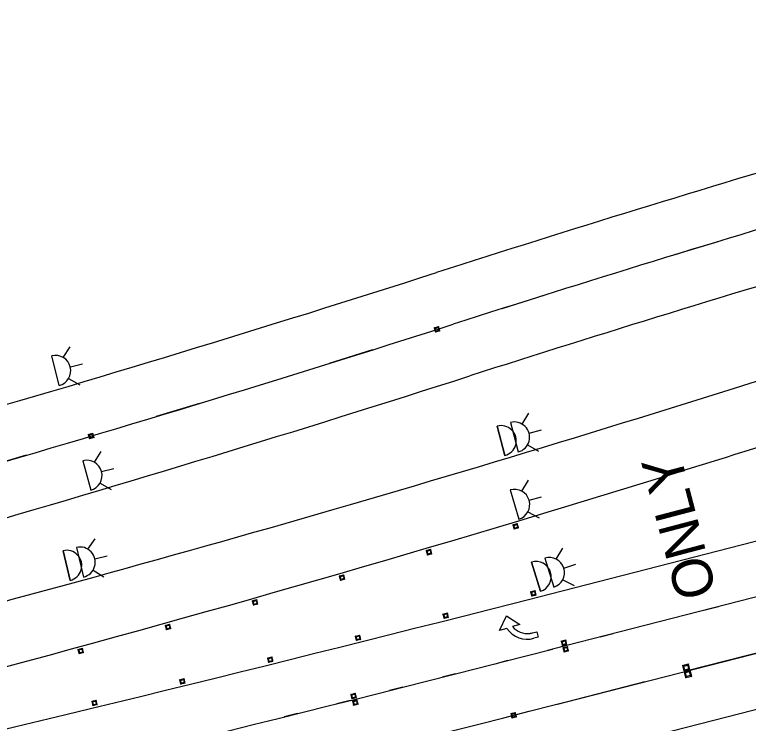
# Model space of a CAD drawing. Extents: x 2471014 to 2497726, y 6959577 to 6980268.
# Drawn here: x 2486454.1 to 2486616.2, y 6968531.5 to 6968688.1 of the extents above; entities that cross this region are included whole.
import ezdxf

# ---------------------------------------------------------------- set-up
doc = ezdxf.new("R2010")
doc.units = 0
for name, color, linetype in [('1', 7, 'Continuous'), ('13', 7, 'Continuous'), ('18', 7, 'Continuous'), ('23', 7, 'Continuous'), ('25', 7, 'Continuous'), ('5', 7, 'Continuous'), ('59', 7, 'Continuous'), ('C-ANNO-NOTE', 7, 'Continuous'), ('C-COMM-IDEN', 7, 'Continuous'), ('Level 30', 7, 'Continuous'), ('Level 40', 7, 'Continuous'), ('p_structure fence', 7, 'Continuous'), ('p_structure wall', 7, 'Continuous'), ('PMK_Del_D-SY_SZ_TYC_CTB', 7, 'Continuous'), ('RDWY_PAVE_XSTREET_FOC', 7, 'Continuous'), ('V7_25', 7, 'Continuous')]:
    doc.layers.add(name, color=color, linetype=linetype)

msp = doc.modelspace()

# ---------------------------------------------------------------- linework, layer by layer
at = {"layer": '1'}
for p, q in [((2486609.48, 6968637.96), (2486599.91, 6968635.05)), ((2486571.26, 6968626.15), (2486561.73, 6968623.14)), ((2486533.14, 6968614.04), (2486523.6, 6968611.05)), ((2486494.93, 6968602.21), (2486485.36, 6968599.31)), ((2486456.61, 6968590.75), (2486447.01, 6968587.94))]:
    msp.add_line(p, q, dxfattribs=at)
at = {"layer": '13'}
for centre, radius, start, end in [((2487770.88, 6964812.37), 3986, 105.11172, 107.76526), ((2485323.83, 6972449.93), 4034, 284.37494, 287.76526), ((2485407.99, 6972430.21), 4024, 286.71744, 287.75395)]:
    msp.add_arc(centre, radius, start, end, dxfattribs=at)
at = {"layer": '18'}
msp.add_line((2486569.97, 6968559.51), (2486887.36, 6968640.85), dxfattribs=at)
for centre, start, end in [((2487770.88, 6964812.37), 105.11172, 107.76526), ((2485323.83, 6972449.93), 284.37494, 287.76526), ((2485407.99, 6972430.21), 284.37494, 287.75395)]:
    msp.add_arc(centre, 4010, start, end, dxfattribs=at)
at = {"layer": '23'}
for p, q in [((2486546.8, 6968618.92), (2486547.76, 6968619.23)), ((2486547.01, 6968618.8), (2486546.8, 6968618.92)), ((2486546.8, 6968618.92), (2486547.1, 6968617.95)), ((2486547.76, 6968619.23), (2486547.66, 6968619.01)), ((2486547.66, 6968619.01), (2486547.86, 6968618.36)), ((2486547.99, 6968618.52), (2486547.76, 6968619.23)), ((2486547.18, 6968618.29), (2486547.01, 6968618.8)), ((2486548.07, 6968618.26), (2486547.1, 6968617.95)), ((2486547.1, 6968617.95), (2486547.22, 6968618.15)), ((2486547.22, 6968618.15), (2486547.18, 6968618.29)), ((2486547.86, 6968618.36), (2486548.07, 6968618.26)), ((2486548.07, 6968618.26), (2486547.99, 6968618.52)), ((2486470.36, 6968595.35), (2486471.33, 6968595.64)), ((2486470.57, 6968595.23), (2486470.36, 6968595.35)), ((2486470.36, 6968595.35), (2486470.65, 6968594.38)), ((2486470.72, 6968594.72), (2486470.57, 6968595.23)), ((2486471.62, 6968594.67), (2486470.65, 6968594.38)), ((2486470.65, 6968594.38), (2486470.77, 6968594.58)), ((2486470.77, 6968594.58), (2486470.72, 6968594.72)), ((2486471.33, 6968595.64), (2486471.22, 6968595.42)), ((2486471.22, 6968595.42), (2486471.41, 6968594.77)), ((2486471.54, 6968594.93), (2486471.33, 6968595.64)), ((2486471.41, 6968594.77), (2486471.62, 6968594.67)), ((2486471.62, 6968594.67), (2486471.54, 6968594.93)), ((2486564.2, 6968575.39), (2486565.17, 6968575.68)), ((2486564.41, 6968575.27), (2486564.2, 6968575.39)), ((2486564.2, 6968575.39), (2486564.49, 6968574.42)), ((2486564.57, 6968574.75), (2486564.41, 6968575.27)), ((2486565.17, 6968575.68), (2486565.06, 6968575.46)), ((2486565.06, 6968575.46), (2486565.25, 6968574.81)), ((2486565.38, 6968574.97), (2486565.17, 6968575.68)), ((2486565.46, 6968574.71), (2486564.49, 6968574.42)), ((2486564.49, 6968574.42), (2486564.61, 6968574.62)), ((2486564.61, 6968574.62), (2486564.57, 6968574.75)), ((2486565.25, 6968574.81), (2486565.46, 6968574.71)), ((2486565.46, 6968574.71), (2486565.38, 6968574.97)), ((2486545.03, 6968569.69), (2486546, 6968569.98)), ((2486545.24, 6968569.57), (2486545.03, 6968569.69)), ((2486545.03, 6968569.69), (2486545.32, 6968568.72)), ((2486545.39, 6968569.05), (2486545.24, 6968569.57)), ((2486546.29, 6968569), (2486545.32, 6968568.72)), ((2486545.32, 6968568.72), (2486545.43, 6968568.92)), ((2486545.43, 6968568.92), (2486545.39, 6968569.05)), ((2486546, 6968569.98), (2486545.89, 6968569.76)), ((2486545.89, 6968569.76), (2486546.08, 6968569.11)), ((2486546.21, 6968569.26), (2486546, 6968569.98)), ((2486546.08, 6968569.11), (2486546.29, 6968569)), ((2486546.29, 6968569), (2486546.21, 6968569.26)), ((2486525.83, 6968564.09), (2486526.81, 6968564.37)), ((2486526.04, 6968563.97), (2486525.83, 6968564.09)), ((2486525.83, 6968564.09), (2486526.11, 6968563.11)), ((2486526.19, 6968563.45), (2486526.04, 6968563.97)), ((2486526.81, 6968564.37), (2486526.7, 6968564.15)), ((2486526.7, 6968564.15), (2486526.88, 6968563.5)), ((2486527.01, 6968563.65), (2486526.81, 6968564.37)), ((2486527.09, 6968563.4), (2486526.11, 6968563.11)), ((2486526.11, 6968563.11), (2486526.23, 6968563.31)), ((2486526.23, 6968563.31), (2486526.19, 6968563.45)), ((2486526.88, 6968563.5), (2486527.09, 6968563.4)), ((2486527.09, 6968563.4), (2486527.01, 6968563.65)), ((2486568.13, 6968560.6), (2486569.12, 6968560.85)), ((2486568.34, 6968560.47), (2486568.13, 6968560.6)), ((2486568.13, 6968560.6), (2486568.38, 6968559.62)), ((2486569.12, 6968560.85), (2486569, 6968560.64)), ((2486569, 6968560.64), (2486569.16, 6968559.98)), ((2486569.3, 6968560.13), (2486569.12, 6968560.85)), ((2486568.47, 6968559.95), (2486568.34, 6968560.47)), ((2486569.37, 6968559.87), (2486568.38, 6968559.62)), ((2486568.38, 6968559.62), (2486568.51, 6968559.82)), ((2486568.51, 6968559.82), (2486568.47, 6968559.95)), ((2486569.16, 6968559.98), (2486569.37, 6968559.87)), ((2486569.37, 6968559.87), (2486569.3, 6968560.13)), ((2486506.61, 6968558.58), (2486507.58, 6968558.86)), ((2486506.82, 6968558.46), (2486506.61, 6968558.58)), ((2486506.61, 6968558.58), (2486506.88, 6968557.61)), ((2486506.97, 6968557.94), (2486506.82, 6968558.46)), ((2486507.86, 6968557.88), (2486506.88, 6968557.61)), ((2486506.88, 6968557.61), (2486507.01, 6968557.81)), ((2486507.01, 6968557.81), (2486506.97, 6968557.94)), ((2486507.58, 6968558.86), (2486507.47, 6968558.64)), ((2486507.47, 6968558.64), (2486507.66, 6968557.99)), ((2486507.79, 6968558.14), (2486507.58, 6968558.86)), ((2486507.66, 6968557.99), (2486507.86, 6968557.88)), ((2486507.86, 6968557.88), (2486507.79, 6968558.14)), ((2486548.75, 6968555.67), (2486549.73, 6968555.92)), ((2486548.96, 6968555.54), (2486548.75, 6968555.67)), ((2486548.75, 6968555.67), (2486549, 6968554.69)), ((2486549.73, 6968555.92), (2486549.62, 6968555.71)), ((2486549.62, 6968555.71), (2486549.78, 6968555.05)), ((2486549.92, 6968555.2), (2486549.73, 6968555.92)), ((2486549.09, 6968555.02), (2486548.96, 6968555.54)), ((2486549.98, 6968554.94), (2486549, 6968554.69)), ((2486549, 6968554.69), (2486549.13, 6968554.88)), ((2486549.13, 6968554.88), (2486549.09, 6968555.02)), ((2486549.78, 6968555.05), (2486549.98, 6968554.94)), ((2486549.98, 6968554.94), (2486549.92, 6968555.2)), ((2486487.36, 6968553.17), (2486488.33, 6968553.44)), ((2486487.57, 6968553.05), (2486487.36, 6968553.17)), ((2486487.36, 6968553.17), (2486487.63, 6968552.19)), ((2486487.71, 6968552.53), (2486487.57, 6968553.05)), ((2486488.61, 6968552.47), (2486487.63, 6968552.19)), ((2486487.75, 6968552.39), (2486487.71, 6968552.53)), ((2486488.33, 6968553.44), (2486488.22, 6968553.23)), ((2486488.22, 6968553.23), (2486488.4, 6968552.57)), ((2486488.53, 6968552.73), (2486488.33, 6968553.44)), ((2486488.4, 6968552.57), (2486488.61, 6968552.47)), ((2486488.61, 6968552.47), (2486488.53, 6968552.73)), ((2486487.63, 6968552.19), (2486487.75, 6968552.39)), ((2486529.36, 6968550.78), (2486530.34, 6968551.03)), ((2486529.57, 6968550.65), (2486529.36, 6968550.78)), ((2486529.36, 6968550.78), (2486529.6, 6968549.8)), ((2486530.34, 6968551.03), (2486530.22, 6968550.82)), ((2486530.22, 6968550.82), (2486530.39, 6968550.16)), ((2486530.52, 6968550.31), (2486530.34, 6968551.03)), ((2486529.7, 6968550.13), (2486529.57, 6968550.65)), ((2486530.59, 6968550.05), (2486529.6, 6968549.8)), ((2486529.6, 6968549.8), (2486529.73, 6968550)), ((2486529.73, 6968550), (2486529.7, 6968550.13)), ((2486530.39, 6968550.16), (2486530.59, 6968550.05)), ((2486530.59, 6968550.05), (2486530.52, 6968550.31)), ((2486574.9, 6968549.69), (2486575.89, 6968549.94)), ((2486575.11, 6968549.56), (2486574.9, 6968549.69)), ((2486574.9, 6968549.69), (2486575.16, 6968548.71)), ((2486575.25, 6968549.04), (2486575.11, 6968549.56)), ((2486575.89, 6968549.94), (2486575.77, 6968549.73)), ((2486575.77, 6968549.73), (2486575.94, 6968549.07)), ((2486576.07, 6968549.22), (2486575.89, 6968549.94)), ((2486576.14, 6968548.96), (2486576.07, 6968549.22)), ((2486468.08, 6968547.86), (2486469.06, 6968548.12)), ((2486468.29, 6968547.73), (2486468.08, 6968547.86)), ((2486468.08, 6968547.86), (2486468.35, 6968546.88)), ((2486468.43, 6968547.21), (2486468.29, 6968547.73)), ((2486469.06, 6968548.12), (2486468.94, 6968547.91)), ((2486468.94, 6968547.91), (2486469.12, 6968547.25)), ((2486469.25, 6968547.4), (2486469.06, 6968548.12)), ((2486576.14, 6968548.96), (2486575.16, 6968548.71)), ((2486575.16, 6968548.71), (2486575.28, 6968548.9)), ((2486575.28, 6968548.9), (2486575.25, 6968549.04)), ((2486575.28, 6968548.24), (2486576.26, 6968548.49)), ((2486575.48, 6968548.11), (2486575.28, 6968548.24)), ((2486575.28, 6968548.24), (2486575.53, 6968547.25)), ((2486575.62, 6968547.59), (2486575.48, 6968548.11)), ((2486575.65, 6968547.45), (2486575.62, 6968547.59)), ((2486575.94, 6968549.07), (2486576.14, 6968548.96)), ((2486576.26, 6968548.49), (2486576.14, 6968548.28)), ((2486576.14, 6968548.28), (2486576.31, 6968547.62)), ((2486576.44, 6968547.77), (2486576.26, 6968548.49)), ((2486576.31, 6968547.62), (2486576.51, 6968547.51)), ((2486576.51, 6968547.51), (2486576.44, 6968547.77)), ((2486469.33, 6968547.14), (2486468.35, 6968546.88)), ((2486468.35, 6968546.88), (2486468.47, 6968547.08)), ((2486468.47, 6968547.08), (2486468.43, 6968547.21)), ((2486469.12, 6968547.25), (2486469.33, 6968547.14)), ((2486469.33, 6968547.14), (2486469.25, 6968547.4)), ((2486509.95, 6968545.94), (2486510.94, 6968546.19)), ((2486510.16, 6968545.81), (2486509.95, 6968545.94)), ((2486509.95, 6968545.94), (2486510.2, 6968544.96)), ((2486510.94, 6968546.19), (2486510.82, 6968545.98)), ((2486510.82, 6968545.98), (2486510.98, 6968545.32)), ((2486511.12, 6968545.47), (2486510.94, 6968546.19)), ((2486576.51, 6968547.51), (2486575.53, 6968547.25)), ((2486575.53, 6968547.25), (2486575.65, 6968547.45)), ((2486510.29, 6968545.29), (2486510.16, 6968545.81)), ((2486511.18, 6968545.21), (2486510.2, 6968544.96)), ((2486510.2, 6968544.96), (2486510.32, 6968545.16)), ((2486510.32, 6968545.16), (2486510.29, 6968545.29)), ((2486510.98, 6968545.32), (2486511.18, 6968545.21)), ((2486511.18, 6968545.21), (2486511.12, 6968545.47)), ((2486601.71, 6968544.33), (2486603.02, 6968544.66)), ((2486601.98, 6968544.18), (2486601.71, 6968544.33)), ((2486601.71, 6968544.33), (2486601.8, 6968543.98)), ((2486603.02, 6968544.66), (2486602.85, 6968544.4)), ((2486602.85, 6968544.4), (2486602.9, 6968544.22)), ((2486603.35, 6968543.35), (2486603.02, 6968544.66)), ((2486601.8, 6968543.98), (2486602.04, 6968543.02)), ((2486602.2, 6968543.3), (2486601.98, 6968544.18)), ((2486603.35, 6968543.35), (2486602.04, 6968543.02)), ((2486602.04, 6968543.02), (2486602.2, 6968543.3)), ((2486602.08, 6968542.87), (2486603.39, 6968543.21)), ((2486602.35, 6968542.72), (2486602.08, 6968542.87)), ((2486602.08, 6968542.87), (2486602.17, 6968542.53)), ((2486602.57, 6968541.85), (2486602.35, 6968542.72)), ((2486602.9, 6968544.22), (2486603.08, 6968543.53)), ((2486603.08, 6968543.53), (2486603.35, 6968543.35)), ((2486603.39, 6968543.21), (2486603.22, 6968542.95)), ((2486603.22, 6968542.95), (2486603.27, 6968542.76)), ((2486603.27, 6968542.76), (2486603.45, 6968542.07)), ((2486603.73, 6968541.9), (2486603.39, 6968543.21)), ((2486490.54, 6968541.15), (2486491.52, 6968541.39)), ((2486490.75, 6968541.02), (2486490.54, 6968541.15)), ((2486490.54, 6968541.15), (2486490.78, 6968540.17)), ((2486491.52, 6968541.39), (2486491.4, 6968541.18)), ((2486491.4, 6968541.18), (2486491.56, 6968540.52)), ((2486491.7, 6968540.67), (2486491.52, 6968541.39)), ((2486602.17, 6968542.53), (2486602.42, 6968541.56)), ((2486603.73, 6968541.9), (2486602.42, 6968541.56)), ((2486602.42, 6968541.56), (2486602.57, 6968541.85)), ((2486603.45, 6968542.07), (2486603.73, 6968541.9)), ((2486490.87, 6968540.5), (2486490.75, 6968541.02)), ((2486491.77, 6968540.41), (2486490.78, 6968540.17)), ((2486490.78, 6968540.17), (2486490.91, 6968540.36)), ((2486490.91, 6968540.36), (2486490.87, 6968540.5)), ((2486491.56, 6968540.52), (2486491.77, 6968540.41)), ((2486491.77, 6968540.41), (2486491.7, 6968540.67)), ((2486528.38, 6968537.91), (2486529.36, 6968538.16)), ((2486528.58, 6968537.78), (2486528.38, 6968537.91)), ((2486528.38, 6968537.91), (2486528.62, 6968536.93)), ((2486529.36, 6968538.16), (2486529.24, 6968537.94)), ((2486529.24, 6968537.94), (2486529.4, 6968537.29)), ((2486529.54, 6968537.43), (2486529.36, 6968538.16)), ((2486471.11, 6968536.4), (2486472.1, 6968536.64)), ((2486471.32, 6968536.27), (2486471.11, 6968536.4)), ((2486471.11, 6968536.4), (2486471.35, 6968535.42)), ((2486471.44, 6968535.75), (2486471.32, 6968536.27)), ((2486472.1, 6968536.64), (2486471.98, 6968536.43)), ((2486471.98, 6968536.43), (2486472.14, 6968535.77)), ((2486472.27, 6968535.92), (2486472.1, 6968536.64)), ((2486528.71, 6968537.26), (2486528.58, 6968537.78)), ((2486529.61, 6968537.17), (2486528.62, 6968536.93)), ((2486528.62, 6968536.93), (2486528.75, 6968537.12)), ((2486528.75, 6968537.12), (2486528.71, 6968537.26)), ((2486528.75, 6968536.46), (2486529.73, 6968536.7)), ((2486528.96, 6968536.33), (2486528.75, 6968536.46)), ((2486528.75, 6968536.46), (2486528.99, 6968535.47)), ((2486529.09, 6968535.81), (2486528.96, 6968536.33)), ((2486529.4, 6968537.29), (2486529.61, 6968537.17)), ((2486529.61, 6968537.17), (2486529.54, 6968537.43)), ((2486529.73, 6968536.7), (2486529.61, 6968536.49)), ((2486529.61, 6968536.49), (2486529.78, 6968535.83)), ((2486529.91, 6968535.98), (2486529.73, 6968536.7)), ((2486472.34, 6968535.66), (2486471.35, 6968535.42)), ((2486471.35, 6968535.42), (2486471.48, 6968535.61)), ((2486471.48, 6968535.61), (2486471.44, 6968535.75)), ((2486472.14, 6968535.77), (2486472.34, 6968535.66)), ((2486472.34, 6968535.66), (2486472.27, 6968535.92)), ((2486529.98, 6968535.72), (2486528.99, 6968535.47)), ((2486528.99, 6968535.47), (2486529.12, 6968535.67)), ((2486529.12, 6968535.67), (2486529.09, 6968535.81)), ((2486529.78, 6968535.83), (2486529.98, 6968535.72)), ((2486529.98, 6968535.72), (2486529.91, 6968535.98)), ((2486563.73, 6968533.66), (2486564.72, 6968533.91)), ((2486563.94, 6968533.55), (2486563.73, 6968533.66)), ((2486563.73, 6968533.66), (2486563.8, 6968533.4)), ((2486563.8, 6968533.4), (2486563.98, 6968532.68)), ((2486564.1, 6968532.89), (2486563.94, 6968533.55)), ((2486564.72, 6968533.91), (2486564.59, 6968533.71)), ((2486564.59, 6968533.71), (2486564.63, 6968533.58)), ((2486564.63, 6968533.58), (2486564.76, 6968533.06)), ((2486564.97, 6968532.93), (2486564.72, 6968533.91)), ((2486564.76, 6968533.06), (2486564.97, 6968532.93)), ((2486564.97, 6968532.93), (2486563.98, 6968532.68)), ((2486563.98, 6968532.68), (2486564.1, 6968532.89))]:
    msp.add_line(p, q, dxfattribs=at)
for points in [[(2486547.86, 6968618.36), (2486547.22, 6968618.15), (2486547.01, 6968618.8), (2486547.66, 6968619.01)], [(2486471.41, 6968594.77), (2486470.77, 6968594.58), (2486470.57, 6968595.23), (2486471.22, 6968595.42)], [(2486565.25, 6968574.81), (2486564.61, 6968574.62), (2486564.41, 6968575.27), (2486565.06, 6968575.46)], [(2486546.08, 6968569.11), (2486545.43, 6968568.92), (2486545.24, 6968569.57), (2486545.89, 6968569.76)], [(2486526.88, 6968563.5), (2486526.23, 6968563.31), (2486526.04, 6968563.97), (2486526.7, 6968564.15)], [(2486569.16, 6968559.98), (2486568.51, 6968559.82), (2486568.34, 6968560.47), (2486569, 6968560.64)], [(2486507.66, 6968557.99), (2486507.01, 6968557.81), (2486506.82, 6968558.46), (2486507.47, 6968558.64)], [(2486549.78, 6968555.05), (2486549.13, 6968554.88), (2486548.96, 6968555.54), (2486549.62, 6968555.71)], [(2486488.4, 6968552.57), (2486487.75, 6968552.39), (2486487.57, 6968553.05), (2486488.22, 6968553.23)], [(2486530.39, 6968550.16), (2486529.73, 6968550), (2486529.57, 6968550.65), (2486530.22, 6968550.82)], [(2486575.94, 6968549.07), (2486575.28, 6968548.9), (2486575.11, 6968549.56), (2486575.77, 6968549.73)], [(2486469.12, 6968547.25), (2486468.47, 6968547.08), (2486468.29, 6968547.73), (2486468.94, 6968547.91)], [(2486576.31, 6968547.62), (2486575.65, 6968547.45), (2486575.48, 6968548.11), (2486576.14, 6968548.28)], [(2486510.98, 6968545.32), (2486510.32, 6968545.16), (2486510.16, 6968545.81), (2486510.82, 6968545.98)], [(2486601.98, 6968544.18), (2486602.85, 6968544.4), (2486603.08, 6968543.53), (2486602.2, 6968543.3)], [(2486602.35, 6968542.72), (2486603.22, 6968542.95), (2486603.45, 6968542.07), (2486602.57, 6968541.85)], [(2486491.56, 6968540.52), (2486490.91, 6968540.36), (2486490.75, 6968541.02), (2486491.4, 6968541.18)], [(2486529.4, 6968537.29), (2486528.75, 6968537.12), (2486528.58, 6968537.78), (2486529.24, 6968537.94)], [(2486472.14, 6968535.77), (2486471.48, 6968535.61), (2486471.32, 6968536.27), (2486471.98, 6968536.43)], [(2486529.78, 6968535.83), (2486529.12, 6968535.67), (2486528.96, 6968536.33), (2486529.61, 6968536.49)], [(2486563.94, 6968533.55), (2486564.59, 6968533.71), (2486564.76, 6968533.06), (2486564.1, 6968532.89)]]:
    msp.add_lwpolyline(points, close=True, dxfattribs=at)
at = {"layer": '25'}
for centre, radius, start, end in [((2485407.99, 6972430.21), 4024, 284.37494, 286.71744), ((2484477.59, 6976736.03), 8440, 281.888901, 284.354026)]:
    msp.add_arc(centre, radius, start, end, dxfattribs=at)
at = {"layer": '5'}
msp.add_line((2486893.32, 6968617.6), (2486602.71, 6968543.12), dxfattribs=at)
msp.add_arc((2479474.04, 6969335.88), 8460, 6.37617, 6.37617, dxfattribs=at)
at = {"layer": '59'}
msp.add_line((2486622.21, 6968560.51), (2486572.95, 6968547.88), dxfattribs=at)
msp.add_arc((2484477.59, 6976736.03), 8452, 281.888901, 284.354075, dxfattribs=at)
at = {"layer": 'C-ANNO-NOTE'}
for centre, radius, start, end in [((2487770.88, 6964812.37), 3998, 105.11172, 107.76526), ((2485323.83, 6972449.93), 4022, 284.37494, 287.76526)]:
    msp.add_arc(centre, radius, start, end, dxfattribs=at)
at = {"layer": 'C-COMM-IDEN'}
for p, q in [((2486566.22, 6968597.67), (2486567.72, 6968600.05)), ((2486563.66, 6968598.01), (2486565.4, 6968591.49)), ((2486562.45, 6968590.7), (2486560.7, 6968597.22)), ((2486560.7, 6968597.22), (2486562.45, 6968590.7)), ((2486567.79, 6968595.62), (2486570.51, 6968596.35)), ((2486567.45, 6968593.06), (2486569.9, 6968591.69)), ((2486470.29, 6968569.98), (2486471.85, 6968572.32)), ((2486467.74, 6968570.39), (2486469.32, 6968563.82)), ((2486573.8, 6968567.81), (2486575.21, 6968570.25)), ((2486466.35, 6968563.11), (2486464.77, 6968569.67)), ((2486464.77, 6968569.67), (2486466.35, 6968563.11)), ((2486471.81, 6968567.89), (2486474.55, 6968568.55)), ((2486570.31, 6968560.7), (2486568.31, 6968567.15)), ((2486568.31, 6968567.15), (2486570.31, 6968560.7)), ((2486571.23, 6968568.05), (2486573.23, 6968561.6)), ((2486575.45, 6968565.83), (2486578.14, 6968566.66)), ((2486471.41, 6968565.34), (2486473.83, 6968563.91)), ((2486575.22, 6968563.25), (2486577.72, 6968561.98))]:
    msp.add_line(p, q, dxfattribs=at)
for centre, start, end in [((2486564.53, 6968594.75), 284.9622, 104.9622), ((2486561.58, 6968593.96), 284.9622, 104.9622), ((2486468.53, 6968567.11), 283.5333, 103.5333), ((2486465.56, 6968566.39), 283.5333, 103.5333), ((2486569.31, 6968563.92), 287.2238, 107.2238), ((2486572.23, 6968564.83), 287.2238, 107.2238)]:
    msp.add_arc(centre, 3.37, start, end, dxfattribs=at)
at = {"layer": 'Level 30'}
for p, q in [((2486464.84, 6968612.35), (2486466.37, 6968614.71)), ((2486463.95, 6968606.18), (2486462.28, 6968612.72)), ((2486466.39, 6968610.28), (2486469.11, 6968610.97)), ((2486466.02, 6968607.72), (2486468.46, 6968606.32))]:
    msp.add_line(p, q, dxfattribs=at)
msp.add_arc((2486463.12, 6968609.45), 3.37, 284.2916, 104.2916, dxfattribs=at)
at = {"layer": 'Level 40'}
for p, q in [((2486609.62, 6968557.28), (2486606.72, 6968556.54)), ((2486598, 6968554.3), (2486595.09, 6968553.56)), ((2486586.37, 6968551.32), (2486583.47, 6968550.58)), ((2486574.75, 6968548.34), (2486571.84, 6968547.6)), ((2486563.12, 6968545.37), (2486560.22, 6968544.63)), ((2486551.49, 6968542.42), (2486548.58, 6968541.69)), ((2486539.86, 6968539.48), (2486536.95, 6968538.75)), ((2486528.22, 6968536.56), (2486525.31, 6968535.84)), ((2486516.57, 6968533.66), (2486513.66, 6968532.94))]:
    msp.add_line(p, q, dxfattribs=at)
at = {"layer": 'p_structure wall'}
for p, q in [((2486561.23, 6968552.02), (2486562.81, 6968555.25)), ((2486562.81, 6968555.25), (2486565.72, 6968553.33)), ((2486562.89, 6968552.47), (2486561.23, 6968552.02)), ((2486565.72, 6968553.33), (2486564.11, 6968552.89)), ((2486568.51, 6968551.5), (2486569.46, 6968551.76)), ((2486569.46, 6968551.76), (2486569.79, 6968550.57)), ((2486569.79, 6968550.57), (2486568.84, 6968550.31))]:
    msp.add_line(p, q, dxfattribs=at)
for radius, start, end in [(5.49, 214.9343, 285.2238), (4.26, 219.61, 277.3525), (4.26, 277.3525, 279.6), (4.26, 279.6, 285.1827)]:
    msp.add_arc((2486567.39, 6968555.61), radius, start, end, dxfattribs=at)
at = {"layer": 'PMK_Del_D-SY_SZ_TYC_CTB'}
for p, q in [((2486471.74, 6968589.21), (2486473.24, 6968591.58)), ((2486469.18, 6968589.55), (2486470.9, 6968583.03)), ((2486473.3, 6968587.15), (2486476.02, 6968587.87)), ((2486566.19, 6968582.82), (2486567.64, 6968585.23)), ((2486472.95, 6968584.59), (2486475.4, 6968583.21)), ((2486563.62, 6968583.11), (2486565.5, 6968576.63)), ((2486567.8, 6968580.81), (2486570.51, 6968581.59)), ((2486567.52, 6968578.24), (2486570, 6968576.92))]:
    msp.add_line(p, q, dxfattribs=at)
for centre, start, end in [((2486470.04, 6968586.29), 284.7764, 104.7764), ((2486564.56, 6968579.87), 286.1343, 106.1343)]:
    msp.add_arc(centre, 3.37, start, end, dxfattribs=at)
at = {"layer": 'RDWY_PAVE_XSTREET_FOC'}
msp.add_line((2486574.04, 6968535.77), (2486593.41, 6968540.74), dxfattribs=at)
at = {"layer": 'V7_25'}
for p, q in [((2486581.89, 6968525.4), (2487110.54, 6968660.88)), ((2486581.89, 6968525.4), (2487110.54, 6968660.88)), ((2486578.91, 6968537.02), (2486789.87, 6968591.09)), ((2486578.91, 6968537.02), (2486789.87, 6968591.09))]:
    msp.add_line(p, q, dxfattribs=at)
msp.add_arc((2484477.59, 6976736.03), 8464, 281.888901, 284.374936, dxfattribs=at)
msp.add_arc((2484477.59, 6976736.03), 8464, 281.888901, 284.374936, dxfattribs=at)

# ---------------------------------------------------------------- texts
at = {"layer": 'p_structure fence'}
msp.add_text('ONLY', height=8.898, rotation=104.7233, dxfattribs=at).set_placement((2486609.33, 6968560.3))

doc.saveas('drawing.dxf')
